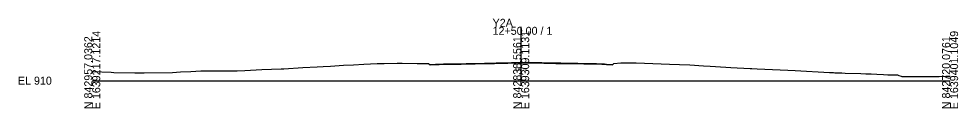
# Model space of a CAD drawing. Extents: x -26 to 303, y -10 to 10517.
# Drawn here: x -25.7 to 302.8, y 1990.3 to 2021.8 of the extents above; entities that cross this region are included whole.
import ezdxf

# ---------------------------------------------------------------- set-up
doc = ezdxf.new("R2010")
doc.units = 0
for name, color, linetype in [('Exist Cross Section Cell', 7, 'Continuous'), ('Exist XS Center Line Elevation Label', 7, 'Continuous'), ('Exist XS Ground Line', 7, 'Continuous'), ('Prop CMT Pvmt Surface Overlay', 7, 'Continuous')]:
    doc.layers.add(name, color=color, linetype=linetype)

msp = doc.modelspace()

# ---------------------------------------------------------------- linework, layer by layer
at = {"layer": 'Exist Cross Section Cell'}
for p, q in [((150, 2000), (150, 2018.91)), ((0, 2000), (150, 2000)), ((150, 2000), (300, 2000))]:
    msp.add_line(p, q, dxfattribs=at)
at = {"layer": 'Exist XS Ground Line'}
msp.add_lwpolyline([(0, 2003.19), (6.65, 2002.98), (7.59, 2002.92), (14.92, 2002.76), (15.67, 2002.77), (18.11, 2002.78), (28.06, 2002.92), (30.84, 2003.06), (34.42, 2003.2), (37.97, 2003.4), (40.72, 2003.41), (50.73, 2003.5), (53.38, 2003.54), (59.35, 2003.89), (66.05, 2004.11), (66.48, 2004.13), (67.03, 2004.16), (73.6, 2004.57), (78.71, 2004.84), (80.73, 2004.99), (83.34, 2005.13), (87.86, 2005.43), (91.37, 2005.58), (94.99, 2005.74), (99.65, 2005.98), (102.11, 2006.08), (106.63, 2006.1), (108.41, 2006.09), (113.68, 2006.07), (117.59, 2006.06), (118.13, 2005.58), (119.99, 2005.65), (121.27, 2005.71), (122.88, 2005.74), (124.43, 2005.76), (124.95, 2005.77), (127.6, 2005.83), (128.22, 2005.84), (129.03, 2005.85), (130.76, 2005.88), (132.76, 2005.91), (133.48, 2005.91), (133.93, 2005.92), (137.18, 2005.99), (138.91, 2006.04), (140.26, 2006.06), (140.69, 2006.07), (141.26, 2006.09), (143.33, 2006.14), (143.7, 2006.15), (144.82, 2006.18), (145.33, 2006.2), (146.59, 2006.22), (149.95, 2006.29), (150.54, 2006.29), (153.17, 2006.26), (153.48, 2006.26), (154.95, 2006.26), (156.08, 2006.23), (156.81, 2006.22), (157.17, 2006.21), (157.9, 2006.19), (159.25, 2006.16), (161.64, 2006.09), (162.08, 2006.08), (162.41, 2006.08), (163.86, 2006.08), (165.71, 2006.03), (167.93, 2006), (168.8, 2006), (169.79, 2005.98), (171.91, 2005.94), (173.87, 2005.91), (175.08, 2005.89), (176.33, 2005.86), (178.24, 2005.84), (179.14, 2005.77), (179.87, 2005.71), (181.94, 2005.57), (182.36, 2006.02), (184.91, 2006.22), (185.28, 2006.25), (189.47, 2006.3), (190.19, 2006.29), (201.9, 2005.8), (205.32, 2005.69), (209.02, 2005.55), (213.79, 2005.25), (216.15, 2005.06), (217.98, 2004.95), (223.28, 2004.61), (230.1, 2004.33), (230.64, 2004.3), (232.52, 2004.21), (243.3, 2003.71), (245.78, 2003.58), (257.85, 2002.86), (258.28, 2002.84), (258.71, 2002.83), (259.19, 2002.82), (259.74, 2002.81), (260.37, 2002.79), (261.2, 2002.76), (262.17, 2002.72), (263.35, 2002.67), (268.79, 2002.51), (270.48, 2002.44), (272.37, 2002.35), (274.35, 2002.27), (276.76, 2002.15), (278.28, 2002.1), (279.98, 2002.05), (281.62, 2002), (282.08, 2001.85), (282.86, 2001.6), (283.17, 2001.48), (284.45, 2001.48), (285.44, 2001.48), (286.22, 2001.48), (287.28, 2001.48), (288.34, 2001.48), (289.03, 2001.48), (290.33, 2001.48), (292.18, 2001.5), (293.92, 2001.5), (295.35, 2001.52), (296.16, 2001.52), (298.51, 2001.54), (299.27, 2001.54), (300, 2001.55)], dxfattribs=at)
at = {"layer": 'Prop CMT Pvmt Surface Overlay'}
msp.add_lwpolyline([(117.99, 2005.7), (119.99, 2005.78), (121.26, 2005.84), (122.88, 2005.87), (124.43, 2005.88), (124.95, 2005.9), (127.6, 2005.96), (128.22, 2005.97), (129.02, 2005.97), (130.76, 2006), (132.76, 2006.03), (133.48, 2006.04), (133.93, 2006.04), (137.18, 2006.11), (138.91, 2006.16), (140.26, 2006.19), (140.69, 2006.2), (141.25, 2006.21), (143.32, 2006.27), (143.69, 2006.28), (144.82, 2006.31), (145.33, 2006.32), (146.59, 2006.34), (149.95, 2006.42), (150.54, 2006.41), (153.17, 2006.38), (153.49, 2006.38), (154.95, 2006.38), (156.09, 2006.36), (156.81, 2006.35), (157.17, 2006.33), (157.9, 2006.32), (159.25, 2006.28), (161.64, 2006.21), (162.08, 2006.21), (162.41, 2006.21), (163.86, 2006.21), (165.72, 2006.16), (167.93, 2006.13), (168.81, 2006.12), (169.79, 2006.11), (171.91, 2006.06), (173.87, 2006.03), (175.08, 2006.01), (176.33, 2005.98), (178.25, 2005.96), (179.15, 2005.89), (179.88, 2005.84), (182.05, 2005.69)], dxfattribs=at)

# ---------------------------------------------------------------- texts
at = {"layer": 'Exist Cross Section Cell'}
for s, p in [('Y2A', (140, 2018.91)), ('12+50.00 / 1', (140, 2016.11)), ('EL 910', (-26, 1998.6))]:
    msp.add_text(s, height=2.8, dxfattribs=at).set_placement(p)
for s, p in [('E 1639217.1214', (2.8, 1990)), ('E 1639309.1131', (152.8, 1990)), ('E 1639401.1049', (302.8, 1990)), ('N 842957.0362', (0, 1990)), ('N 842838.5561', (150, 1990)), ('N 842720.0761', (300, 1990))]:
    msp.add_text(s, height=2.8, rotation=90, dxfattribs=at).set_placement(p)
at = {"layer": 'Exist XS Center Line Elevation Label'}
msp.add_text('916.29', height=1, dxfattribs=at).set_placement((147.82, 2003.45))

doc.saveas('drawing.dxf')
